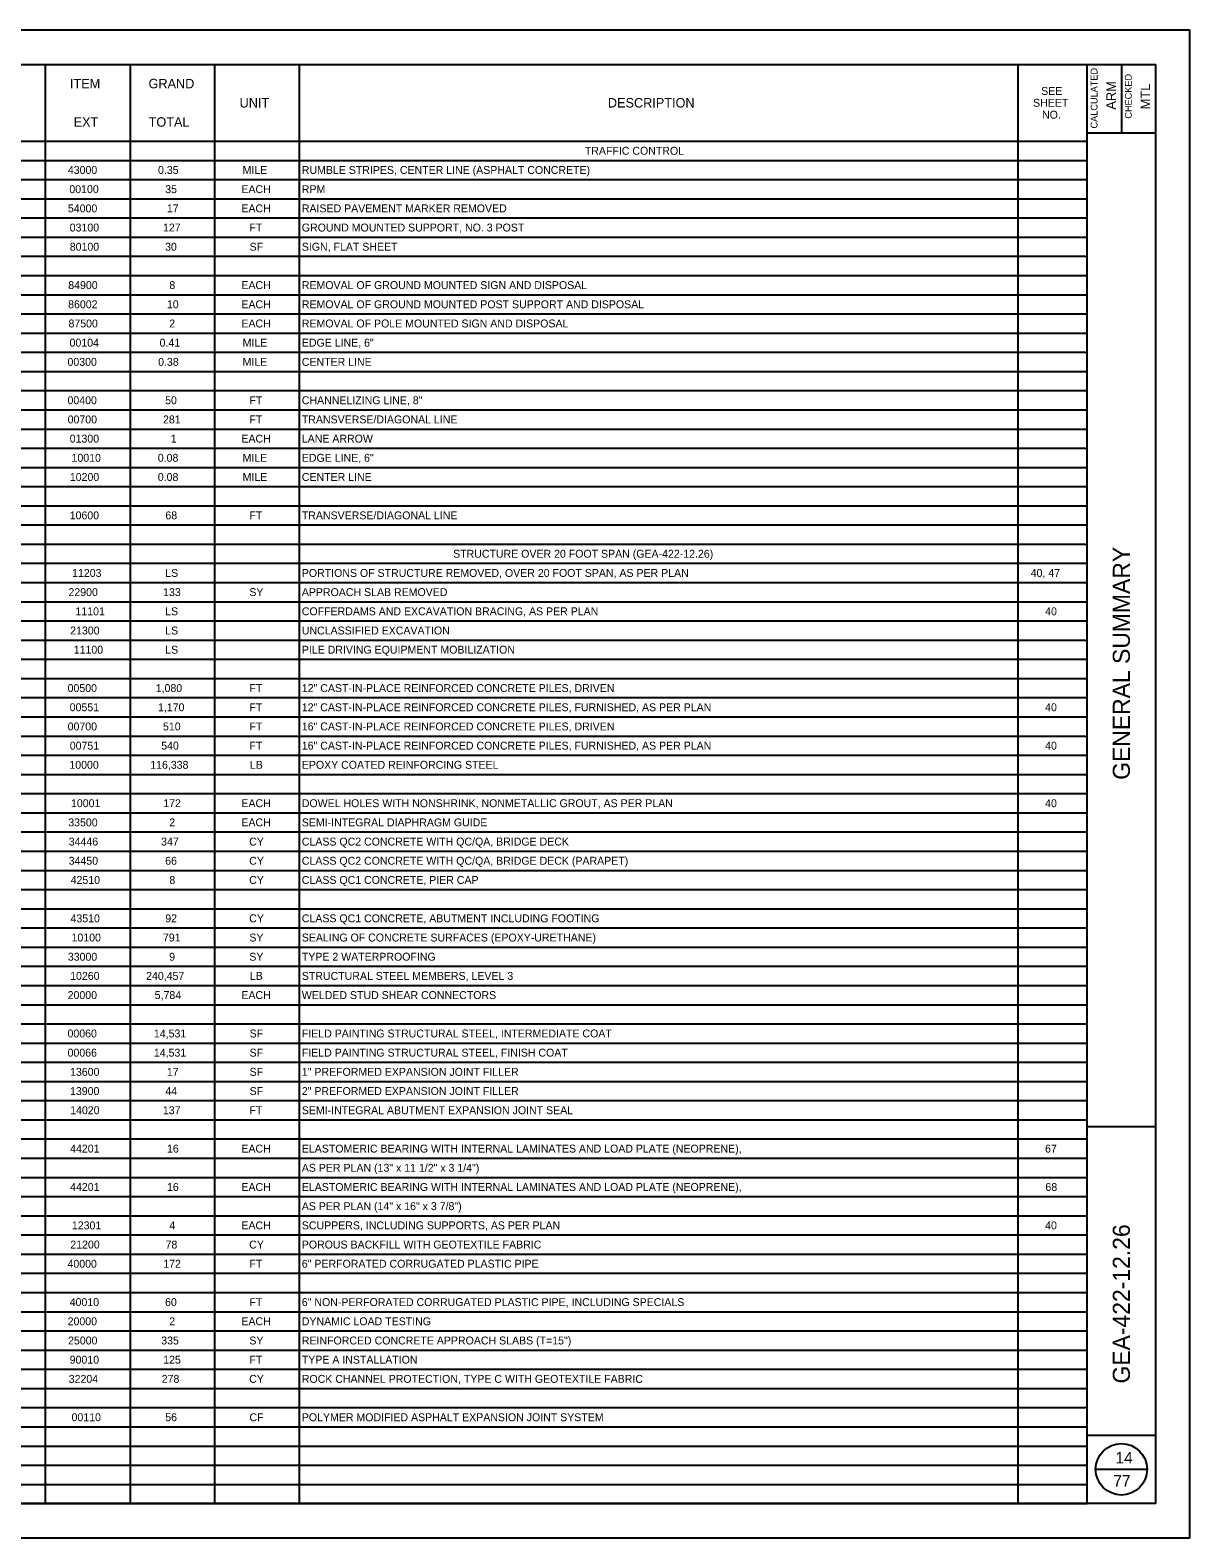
# Model space of a CAD drawing. Extents: x 0 to 34, y 0 to 22.
# Drawn here: x 17.07 to 34, y 0 to 22 of the extents above; entities that cross this region are included whole.
import ezdxf

# ---------------------------------------------------------------- set-up
doc = ezdxf.new("R2010")
doc.units = 0
for name, color, linetype in [('SH_Border', 7, 'Continuous'), ('SH_Cut_Line', 7, 'Continuous'), ('SH_Data', 7, 'Continuous'), ('SH_Text', 7, 'Continuous')]:
    doc.layers.add(name, color=color, linetype=linetype)

msp = doc.modelspace()

# ---------------------------------------------------------------- linework, layer by layer
at = {"layer": 'SH_Border'}
for p, q in [((32.5, 0.5), (32.5, 21.5)), ((33, 21.5), (33, 20.5)), ((32.5, 20.5), (33.5, 20.5)), ((32.5, 6), (33.5, 6)), ((32.5, 1.5), (33.5, 1.5))]:
    msp.add_line(p, q, dxfattribs=at)
msp.add_lwpolyline([(2, 21.5), (33.5, 21.5), (33.5, 0.5), (2, 0.5)], close=True, dxfattribs=at)
at = {"layer": 'SH_Cut_Line'}
msp.add_lwpolyline([(0, 0), (34, 0), (34, 22), (0, 22)], close=True, dxfattribs=at)
at = {"layer": 'SH_Data'}
msp.add_line((32.625, 1), (33.375, 1), dxfattribs=at)
msp.add_circle((33, 1), 0.375, dxfattribs=at)
at = {"layer": 'SH_Text'}
for p, q in [((2, 21.5), (32.5, 21.5)), ((17.299, 0.5), (17.299, 21.5)), ((18.535, 0.5), (18.535, 21.5)), ((19.77, 0.5), (19.77, 21.5)), ((21.005, 0.5), (21.005, 21.5)), ((31.495, 0.5), (31.495, 21.5)), ((32.5, 0.5), (32.5, 21.5)), ((14.055, 20.38), (32.5, 20.38)), ((19.77, 20.38), (32.5, 20.38)), ((2, 20.1), (32.5, 20.1)), ((2, 19.82), (32.5, 19.82)), ((2, 19.54), (32.5, 19.54)), ((2, 19.26), (32.5, 19.26)), ((2, 18.98), (32.5, 18.98)), ((2, 18.7), (32.5, 18.7)), ((2, 18.42), (32.5, 18.42)), ((2, 18.14), (32.5, 18.14)), ((2, 17.86), (32.5, 17.86)), ((2, 17.58), (32.5, 17.58)), ((2, 17.3), (32.5, 17.3)), ((2, 17.02), (32.5, 17.02)), ((2, 16.74), (32.5, 16.74)), ((2, 16.46), (32.5, 16.46)), ((2, 16.18), (32.5, 16.18)), ((2, 15.9), (32.5, 15.9)), ((2, 15.62), (32.5, 15.62)), ((2, 15.34), (32.5, 15.34)), ((2, 15.06), (32.5, 15.06)), ((2, 14.78), (32.5, 14.78)), ((2, 14.5), (32.5, 14.5)), ((2, 14.22), (32.5, 14.22)), ((2, 13.94), (32.5, 13.94)), ((2, 13.66), (32.5, 13.66)), ((2, 13.38), (32.5, 13.38)), ((2, 13.1), (32.5, 13.1)), ((2, 12.82), (32.5, 12.82)), ((2, 12.54), (32.5, 12.54)), ((2, 12.26), (32.5, 12.26)), ((2, 11.98), (32.5, 11.98)), ((2, 11.7), (32.5, 11.7)), ((2, 11.42), (32.5, 11.42)), ((2, 11.14), (32.5, 11.14)), ((2, 10.86), (32.5, 10.86)), ((2, 10.58), (32.5, 10.58)), ((2, 10.3), (32.5, 10.3)), ((2, 10.02), (32.5, 10.02)), ((2, 9.74), (32.5, 9.74)), ((2, 9.46), (32.5, 9.46)), ((2, 9.18), (32.5, 9.18)), ((2, 8.9), (32.5, 8.9)), ((2, 8.62), (32.5, 8.62)), ((2, 8.34), (32.5, 8.34)), ((2, 8.06), (32.5, 8.06)), ((2, 7.78), (32.5, 7.78)), ((2, 7.5), (32.5, 7.5)), ((2, 7.22), (32.5, 7.22)), ((2, 6.94), (32.5, 6.94)), ((2, 6.66), (32.5, 6.66)), ((2, 6.38), (32.5, 6.38)), ((2, 6.1), (32.5, 6.1)), ((2, 5.82), (32.5, 5.82)), ((2, 5.54), (32.5, 5.54)), ((2, 5.26), (32.5, 5.26)), ((2, 4.98), (32.5, 4.98)), ((2, 4.7), (32.5, 4.7)), ((2, 4.42), (32.5, 4.42)), ((2, 4.14), (32.5, 4.14)), ((2, 3.86), (32.5, 3.86)), ((2, 3.58), (32.5, 3.58)), ((2, 3.3), (32.5, 3.3)), ((2, 3.02), (32.5, 3.02)), ((2, 2.74), (32.5, 2.74)), ((2, 2.46), (32.5, 2.46)), ((2, 2.18), (32.5, 2.18)), ((2, 1.9), (32.5, 1.9)), ((2, 1.62), (32.5, 1.62)), ((2, 1.34), (32.5, 1.34)), ((2, 1.06), (32.5, 1.06)), ((2, 0.78), (32.5, 0.78)), ((2, 0.5), (32.5, 0.5))]:
    msp.add_line(p, q, dxfattribs=at)

# ---------------------------------------------------------------- texts
at = {"layer": 'SH_Data'}
for s, height, p in [('CALCULATED', 0.1, (32.652, 20.565)), ('CHECKED', 0.1, (33.152, 20.708)), ('ARM', 0.14, (32.92, 20.84)), ('MTL', 0.14, (33.42, 20.844)), ('GENERAL SUMMARY', 0.25, (33.125, 11.061)), ('GEA-422-12.26', 0.25, (33.125, 2.252))]:
    msp.add_text(s, height=height, rotation=90, dxfattribs=at).set_placement(p)
for s, p in [('14', (32.914, 1.085)), ('77', (32.882, 0.745))]:
    msp.add_text(s, height=0.17, dxfattribs=at).set_placement(p)
at = {"layer": 'SH_Text'}
for s, height, p in [('ITEM', 0.1384, (17.654, 21.151)), ('GRAND', 0.1384, (18.801, 21.151)), ('SEE', 0.1153, (31.83, 21.055)), ('UNIT', 0.1384, (20.13, 20.871)), ('DESCRIPTION', 0.13841, (25.506, 20.871)), ('SHEET', 0.1153, (31.712, 20.882)), ('EXT', 0.1384, (17.707, 20.591)), ('TOTAL', 0.1384, (18.802, 20.591)), ('NO.', 0.1153, (31.843, 20.709)), ('TRAFFIC CONTROL', 0.11534, (25.169, 20.182)), ('RUMBLE STRIPES, CENTER LINE (ASPHALT CONCRETE) ', 0.11534, (21.038, 19.902)), ('43000', 0.1153, (17.623, 19.902)), ('0.35', 0.1153, (18.939, 19.902)), ('MILE', 0.1153, (20.174, 19.902)), ('00100', 0.1153, (17.645, 19.622)), ('35', 0.1153, (19.044, 19.622)), ('EACH', 0.1153, (20.156, 19.622)), ('RPM ', 0.1153, (21.038, 19.622)), ('54000', 0.1153, (17.624, 19.342)), ('17', 0.1153, (19.068, 19.342)), ('EACH', 0.1153, (20.156, 19.342)), ('RAISED PAVEMENT MARKER REMOVED ', 0.11534, (21.038, 19.342)), ('03100', 0.1153, (17.65, 19.062)), ('127', 0.1153, (19.012, 19.062)), ('FT', 0.1153, (20.272, 19.062)), ('GROUND MOUNTED SUPPORT, NO. 3 POST ', 0.11534, (21.038, 19.062)), ('80100', 0.1153, (17.651, 18.782)), ('30', 0.1153, (19.042, 18.782)), ('SF', 0.1153, (20.276, 18.782)), ('SIGN, FLAT SHEET ', 0.11534, (21.038, 18.782)), ('84900', 0.1153, (17.629, 18.222)), ('8', 0.115, (19.105, 18.222)), ('EACH', 0.1153, (20.156, 18.222)), ('REMOVAL OF GROUND MOUNTED SIGN AND DISPOSAL ', 0.11534, (21.038, 18.222)), ('86002', 0.1153, (17.627, 17.942)), ('10', 0.1153, (19.069, 17.942)), ('EACH', 0.1153, (20.156, 17.942)), ('REMOVAL OF GROUND MOUNTED POST SUPPORT AND DISPOSAL ', 0.11534, (21.038, 17.942)), ('87500', 0.1153, (17.632, 17.662)), ('2', 0.115, (19.103, 17.662)), ('EACH', 0.1153, (20.156, 17.662)), ('REMOVAL OF POLE MOUNTED SIGN AND DISPOSAL ', 0.11534, (21.038, 17.662)), ('00104', 0.1153, (17.648, 17.382)), ('0.41', 0.1153, (18.962, 17.382)), ('MILE', 0.1153, (20.174, 17.382)), ('EDGE LINE, 6"', 0.11534, (21.038, 17.382)), ('00300', 0.1153, (17.618, 17.102)), ('0.38', 0.1153, (18.941, 17.102)), ('MILE', 0.1153, (20.174, 17.102)), ('CENTER LINE ', 0.11534, (21.038, 17.102)), ('00400', 0.1153, (17.618, 16.542)), ('50', 0.1153, (19.043, 16.542)), ('FT', 0.1153, (20.272, 16.542)), ('CHANNELIZING LINE, 8" ', 0.11534, (21.038, 16.542)), ('00700', 0.1153, (17.62, 16.262)), ('281', 0.1153, (19.012, 16.262)), ('FT', 0.1153, (20.272, 16.262)), ('TRANSVERSE/DIAGONAL LINE ', 0.11534, (21.038, 16.262)), ('01300', 0.1153, (17.65, 15.982)), ('1', 0.115, (19.125, 15.982)), ('EACH', 0.1153, (20.156, 15.982)), ('LANE ARROW ', 0.11534, (21.038, 15.982)), ('10010', 0.1153, (17.677, 15.702)), ('0.08', 0.1153, (18.936, 15.702)), ('MILE', 0.1153, (20.174, 15.702)), ('EDGE LINE, 6" ', 0.11534, (21.038, 15.702)), ('10200', 0.1153, (17.652, 15.422)), ('0.08', 0.1153, (18.936, 15.422)), ('MILE', 0.1153, (20.174, 15.422)), ('CENTER LINE ', 0.11534, (21.038, 15.422)), ('10600', 0.1153, (17.65, 14.862)), ('68', 0.1153, (19.047, 14.862)), ('FT', 0.1153, (20.272, 14.862)), ('TRANSVERSE/DIAGONAL LINE ', 0.11534, (21.038, 14.862)), ('STRUCTURE OVER 20 FOOT SPAN (GEA-422-12.26)', 0.11534, (23.246, 14.302)), ('11203', 0.1153, (17.685, 14.022)), ('LS', 0.1153, (19.044, 14.022)), ('PORTIONS OF STRUCTURE REMOVED, OVER 20 FOOT SPAN, AS PER PLAN', 0.11534, (21.038, 14.022)), ('40, 47', 0.1153, (31.677, 14.022)), ('22900', 0.1153, (17.632, 13.742)), ('133', 0.1153, (19.013, 13.742)), ('SY', 0.1153, (20.272, 13.742)), ('APPROACH SLAB REMOVED', 0.11534, (21.038, 13.742)), ('11101', 0.1153, (17.734, 13.462)), ('LS', 0.1153, (19.044, 13.462)), ('COFFERDAMS AND EXCAVATION BRACING, AS PER PLAN', 0.11534, (21.038, 13.462)), ('40', 0.1153, (31.888, 13.462)), ('21300', 0.1153, (17.657, 13.182)), ('LS', 0.1153, (19.044, 13.182)), ('UNCLASSIFIED EXCAVATION', 0.11534, (21.038, 13.182)), ('11100', 0.1153, (17.709, 12.902)), ('LS', 0.1153, (19.044, 12.902)), ('PILE DRIVING EQUIPMENT MOBILIZATION', 0.11534, (21.038, 12.902)), ('00500', 0.1153, (17.619, 12.342)), ('1,080', 0.1153, (18.906, 12.342)), ('FT', 0.1153, (20.272, 12.342)), ('12" CAST-IN-PLACE REINFORCED CONCRETE PILES, DRIVEN', 0.11534, (21.038, 12.342)), ('00551', 0.1153, (17.65, 12.062)), ('1,170', 0.1153, (18.939, 12.062)), ('FT', 0.1153, (20.272, 12.062)), ('12" CAST-IN-PLACE REINFORCED CONCRETE PILES, FURNISHED, AS PER PLAN', 0.11534, (21.038, 12.062)), ('40', 0.1153, (31.888, 12.062)), ('00700', 0.1153, (17.62, 11.782)), ('510', 0.1153, (19.012, 11.782)), ('FT', 0.1153, (20.272, 11.782)), ('16" CAST-IN-PLACE REINFORCED CONCRETE PILES, DRIVEN', 0.11534, (21.038, 11.782)), ('00751', 0.1153, (17.651, 11.502)), ('540', 0.1153, (18.986, 11.502)), ('FT', 0.1153, (20.272, 11.502)), ('16" CAST-IN-PLACE REINFORCED CONCRETE PILES, FURNISHED, AS PER PLAN', 0.11534, (21.038, 11.502)), ('40', 0.1153, (31.888, 11.502)), ('10000', 0.1153, (17.645, 11.222)), ('116,338', 0.1153, (18.826, 11.222)), ('LB', 0.1153, (20.28, 11.222)), ('EPOXY COATED REINFORCING STEEL', 0.11534, (21.038, 11.222)), ('10001', 0.1153, (17.669, 10.662)), ('172', 0.1153, (19.016, 10.662)), ('EACH', 0.1153, (20.156, 10.662)), ('DOWEL HOLES WITH NONSHRINK, NONMETALLIC GROUT, AS PER PLAN', 0.11534, (21.038, 10.662)), ('40', 0.1153, (31.888, 10.662)), ('33500', 0.1153, (17.629, 10.382)), ('2', 0.115, (19.103, 10.382)), ('EACH', 0.1153, (20.156, 10.382)), ('SEMI-INTEGRAL DIAPHRAGM GUIDE', 0.11534, (21.038, 10.382)), ('34446', 0.1153, (17.636, 10.102)), ('347', 0.1153, (18.984, 10.102)), ('CY', 0.1153, (20.27, 10.102)), ('CLASS QC2 CONCRETE WITH QC/QA, BRIDGE DECK', 0.11534, (21.038, 10.102)), ('34450', 0.1153, (17.635, 9.822)), ('66', 0.1153, (19.044, 9.822)), ('CY', 0.1153, (20.27, 9.822)), ('CLASS QC2 CONCRETE WITH QC/QA, BRIDGE DECK (PARAPET)', 0.11534, (21.038, 9.822)), ('42510', 0.1153, (17.664, 9.542)), ('8', 0.115, (19.105, 9.542)), ('CY', 0.1153, (20.27, 9.542)), ('CLASS QC1 CONCRETE, PIER CAP', 0.11534, (21.038, 9.542)), ('43510', 0.1153, (17.662, 8.982)), ('92', 0.1153, (19.045, 8.982)), ('CY', 0.1153, (20.27, 8.982)), ('CLASS QC1 CONCRETE, ABUTMENT INCLUDING FOOTING', 0.11534, (21.038, 8.982)), ('10100', 0.1153, (17.677, 8.702)), ('791', 0.1153, (19.011, 8.702)), ('SY', 0.1153, (20.272, 8.702)), ('SEALING OF CONCRETE SURFACES (EPOXY-URETHANE)', 0.11534, (21.038, 8.702)), ('33000', 0.1153, (17.623, 8.422)), ('9', 0.115, (19.102, 8.422)), ('SY', 0.1153, (20.272, 8.422)), ('TYPE 2 WATERPROOFING', 0.11534, (21.038, 8.422)), ('10260', 0.1153, (17.657, 8.142)), ('240,457', 0.1153, (18.765, 8.142)), ('LB', 0.1153, (20.28, 8.142)), ('STRUCTURAL STEEL MEMBERS, LEVEL 3', 0.11534, (21.038, 8.142)), ('20000', 0.1153, (17.62, 7.862)), ('5,784', 0.1153, (18.891, 7.862)), ('EACH', 0.1153, (20.156, 7.862)), ('WELDED STUD SHEAR CONNECTORS', 0.11534, (21.038, 7.862)), ('00060', 0.1153, (17.618, 7.302)), ('14,531', 0.1153, (18.879, 7.302)), ('SF', 0.1153, (20.276, 7.302)), ('FIELD PAINTING STRUCTURAL STEEL, INTERMEDIATE COAT', 0.11534, (21.038, 7.302)), ('00066', 0.1153, (17.619, 7.022)), ('14,531', 0.1153, (18.879, 7.022)), ('SF', 0.1153, (20.276, 7.022)), ('FIELD PAINTING STRUCTURAL STEEL, FINISH COAT', 0.11534, (21.038, 7.022)), ('13600', 0.1153, (17.655, 6.742)), ('17', 0.1153, (19.068, 6.742)), ('SF', 0.1153, (20.276, 6.742)), ('1" PREFORMED EXPANSION JOINT FILLER', 0.11534, (21.038, 6.742)), ('13900', 0.1153, (17.655, 6.462)), ('44', 0.1153, (19.046, 6.462)), ('SF', 0.1153, (20.276, 6.462)), ('2" PREFORMED EXPANSION JOINT FILLER', 0.11534, (21.038, 6.462)), ('14020', 0.1153, (17.657, 6.182)), ('137', 0.1153, (19.01, 6.182)), ('FT', 0.1153, (20.272, 6.182)), ('SEMI-INTEGRAL ABUTMENT EXPANSION JOINT SEAL', 0.11534, (21.038, 6.182)), ('44201', 0.1153, (17.656, 5.622)), ('16', 0.1153, (19.07, 5.622)), ('EACH', 0.1153, (20.156, 5.622)), ('ELASTOMERIC BEARING WITH INTERNAL LAMINATES AND LOAD PLATE (NEOPRENE),', 0.11534, (21.038, 5.622)), ('67', 0.1153, (31.887, 5.622)), ('AS PER PLAN (13" x 11 1/2" x 3 1/4")', 0.11534, (21.038, 5.342)), ('44201', 0.1153, (17.656, 5.062)), ('16', 0.1153, (19.07, 5.062)), ('EACH', 0.1153, (20.156, 5.062)), ('ELASTOMERIC BEARING WITH INTERNAL LAMINATES AND LOAD PLATE (NEOPRENE),', 0.11534, (21.038, 5.062)), ('68', 0.1153, (31.892, 5.062)), ('AS PER PLAN (14" x 16" x 3 7/8")', 0.11534, (21.038, 4.782)), ('12301', 0.1153, (17.682, 4.502)), ('4', 0.115, (19.104, 4.502)), ('EACH', 0.1153, (20.156, 4.502)), ('SCUPPERS, INCLUDING SUPPORTS, AS PER PLAN', 0.11534, (21.038, 4.502)), ('40', 0.1153, (31.888, 4.502)), ('21200', 0.1153, (17.659, 4.222)), ('78', 0.1153, (19.049, 4.222)), ('CY', 0.1153, (20.27, 4.222)), ('POROUS BACKFILL WITH GEOTEXTILE FABRIC', 0.11534, (21.038, 4.222)), ('40000', 0.1153, (17.618, 3.942)), ('172', 0.1153, (19.016, 3.942)), ('FT', 0.1153, (20.272, 3.942)), ('6" PERFORATED CORRUGATED PLASTIC PIPE', 0.11534, (21.038, 3.942)), ('40010', 0.1153, (17.65, 3.382)), ('60', 0.1153, (19.042, 3.382)), ('FT', 0.1153, (20.272, 3.382)), ('6" NON-PERFORATED CORRUGATED PLASTIC PIPE, INCLUDING SPECIALS', 0.11534, (21.038, 3.382)), ('20000', 0.1153, (17.62, 3.102)), ('2', 0.115, (19.103, 3.102)), ('EACH', 0.1153, (20.156, 3.102)), ('DYNAMIC LOAD TESTING', 0.11534, (21.038, 3.102)), ('25000', 0.1153, (17.626, 2.822)), ('335', 0.1153, (18.986, 2.822)), ('SY', 0.1153, (20.272, 2.822)), ('REINFORCED CONCRETE APPROACH SLABS (T=15")', 0.11534, (21.038, 2.822)), ('90010', 0.1153, (17.65, 2.542)), ('125', 0.1153, (19.015, 2.542)), ('FT', 0.1153, (20.272, 2.542)), ('TYPE A INSTALLATION', 0.11534, (21.038, 2.542)), ('32204', 0.1153, (17.636, 2.262)), ('278', 0.1153, (18.993, 2.262)), ('CY', 0.1153, (20.27, 2.262)), ('ROCK CHANNEL PROTECTION, TYPE C WITH GEOTEXTILE FABRIC', 0.11534, (21.038, 2.262)), ('00110', 0.1153, (17.677, 1.702)), ('56', 0.1153, (19.045, 1.702)), ('CF', 0.1153, (20.274, 1.702)), ('POLYMER MODIFIED ASPHALT EXPANSION JOINT SYSTEM', 0.11534, (21.038, 1.702))]:
    msp.add_text(s, height=height, dxfattribs=at).set_placement(p)

doc.saveas('drawing.dxf')
